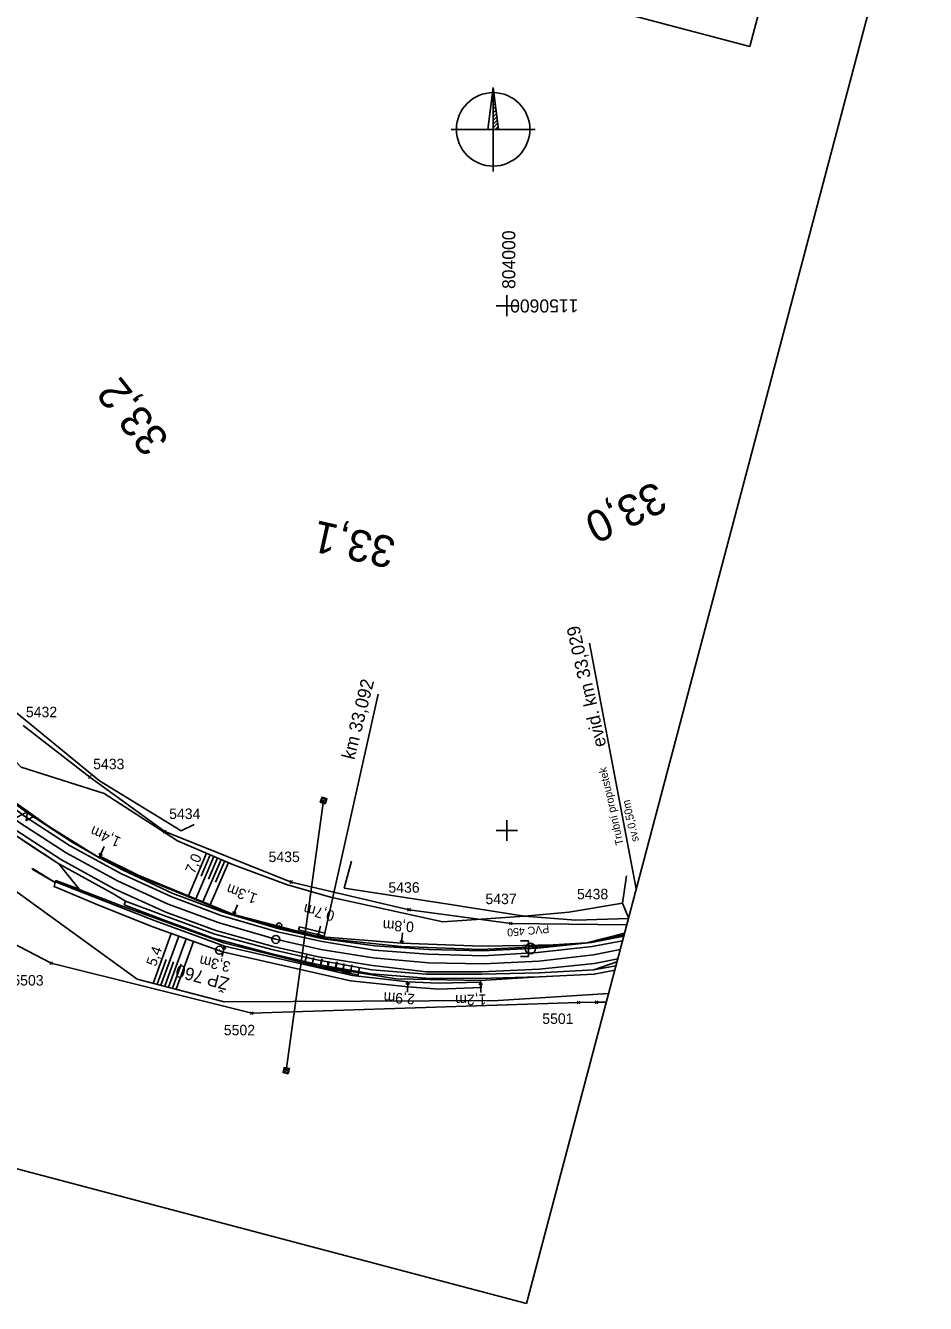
# Model space of a CAD drawing. Extents: x -805011 to -803920, y -1150790 to -1150234.
# Drawn here: x -804091.7 to -803920.3, y -1150790.1 to -1150546.6 of the extents above; entities that cross this region are included whole.
import ezdxf

# ---------------------------------------------------------------- set-up
doc = ezdxf.new("R2010")
doc.units = 0
for name, color, linetype in [('0381KM032-037P - Vrstva 1', 7, 'Continuous'), ('0381KM032-037P - Vrstva 11', 7, 'Continuous'), ('0381KM032-037P - Vrstva 13', 7, 'Continuous'), ('0381KM032-037P - Vrstva 17', 7, 'Continuous'), ('0381KM032-037P - Vrstva 19', 7, 'Continuous'), ('0381KM032-037P - Vrstva 25', 7, 'Continuous'), ('0381KM032-037P - Vrstva 4', 7, 'Continuous'), ('0381KM032-037P - Vrstva 43', 7, 'Continuous'), ('0381KM032-037P - Vrstva 44', 7, 'Continuous'), ('0381KM032-037P - Vrstva 48', 7, 'Continuous'), ('0381KM032-037P - Vrstva 49', 7, 'Continuous'), ('0381KM032-037P - Vrstva 50', 7, 'Continuous'), ('0381KM032-037P - Vrstva 7', 7, 'Continuous'), ('0381KM032-037P - Vrstva 9', 7, 'Continuous'), ('Default', 7, 'Continuous'), ('formát', 7, 'Continuous'), ('krizky_1000 - souradnice', 7, 'Continuous'), ('krizky_1000 - Vrstva 1', 7, 'Continuous'), ('szdc - hran DP', 7, 'Continuous'), ('szdc - szdc_cislo', 7, 'Continuous'), ('szdc - szdc_krizek', 7, 'Continuous'), ('vyt_sit - stávající', 7, 'Continuous')]:
    doc.layers.add(name, color=color, linetype=linetype)

msp = doc.modelspace()

# ---------------------------------------------------------------- linework, layer by layer
at = {"layer": '0381KM032-037P - Vrstva 1'}
msp.add_lwpolyline([(-803978.41, -1150722.71), (-803983.51, -1150723.68), (-803993.92, -1150724.91), (-804004.46, -1150725.42), (-804014.95, -1150725.21), (-804025.47, -1150724.25), (-804035.41, -1150722.67), (-804044.08, -1150720.74), (-804054.77, -1150717.61), (-804064.47, -1150714.03), (-804074.16, -1150709.61), (-804083.95, -1150704.25), (-804092.73, -1150698.52), (-804098.22, -1150694.46), (-804106.33, -1150687.73), (-804113.82, -1150680.6), (-804121.06, -1150672.62)], dxfattribs=at)
at = {"layer": '0381KM032-037P - Vrstva 11'}
for p, q in [((-804034.26, -1150693.99), (-804035.54, -1150694.57)), ((-804034.75, -1150693.8), (-804035.36, -1150694.08)), ((-804034.44, -1150694.48), (-804035.04, -1150694.76)), ((-804041.41, -1150745.38), (-804042.6, -1150746.13)), ((-804041.93, -1150745.26), (-804042.49, -1150745.62)), ((-804041.53, -1150745.9), (-804042.08, -1150746.25))]:
    msp.add_line(p, q, dxfattribs=at)
for points in [[(-804034.6, -1150694.92), (-804035.54, -1150694.57), (-804035.19, -1150693.64), (-804034.25, -1150693.98)], [(-804041.63, -1150746.35), (-804042.61, -1150746.13), (-804042.39, -1150745.16), (-804041.41, -1150745.38)]]:
    msp.add_lwpolyline(points, close=True, dxfattribs=at)
at = {"layer": '0381KM032-037P - Vrstva 13'}
for p, q in [((-804076.66, -1150703.07), (-804077.51, -1150704.88)), ((-804090.31, -1150707.26), (-804090.39, -1150707.37)), ((-804086.01, -1150709.9), (-804090.31, -1150707.26)), ((-804090.39, -1150707.37), (-804086.01, -1150709.92)), ((-804086.01, -1150709.9), (-804085.89, -1150709.55)), ((-804085.98, -1150709.77), (-804085.89, -1150709.55)), ((-804086.01, -1150709.92), (-804086.01, -1150709.9)), ((-804051.27, -1150714.14), (-804052.03, -1150715.99)), ((-804035.82, -1150720.44), (-804051.93, -1150716.22)), ((-804035.5, -1150718.26), (-804035.97, -1150720.21)), ((-804019.87, -1150719.5), (-804020.03, -1150721.49)), ((-804054.2, -1150724.02), (-804053.75, -1150722.07)), ((-804018.95, -1150730.84), (-804018.83, -1150728.85)), ((-804004.99, -1150728.9), (-804004.87, -1150729.93)), ((-804004.95, -1150730.9), (-804004.99, -1150728.9))]:
    msp.add_line(p, q, dxfattribs=at)
for points in [[(-804052.03, -1150715.99), (-804070.24, -1150708.52), (-804077.53, -1150704.87), (-804077.68, -1150705.14), (-804070.39, -1150708.64), (-804052.3, -1150716.03), (-804051.93, -1150716.22)], [(-804077.57, -1150704.3), (-804077.51, -1150704.88), (-804077.03, -1150704.55)], [(-804085.89, -1150709.55), (-804073.05, -1150714.48), (-804053.9, -1150721.4), (-804036.64, -1150725.7), (-804021.1, -1150728.28), (-804004.99, -1150728.61), (-804004.87, -1150729.93)], [(-804085.98, -1150709.77), (-804086.01, -1150709.92), (-804086.24, -1150710.7)], [(-804004.87, -1150729.93), (-804012.98, -1150730.26), (-804018.76, -1150729.81), (-804029.79, -1150728.64), (-804054.15, -1150723.15), (-804067.44, -1150718.36), (-804077.42, -1150714.36), (-804086.24, -1150710.7)], [(-804004.99, -1150728.9), (-804013.04, -1150729.07), (-804018.83, -1150728.85), (-804029.4, -1150727.62), (-804053.75, -1150722.07), (-804066.98, -1150717.23), (-804077.05, -1150713.27), (-804085.98, -1150709.77)], [(-804072.89, -1150714.19), (-804072.63, -1150713.44), (-804065.3, -1150716.18), (-804055.61, -1150719.76), (-804044.75, -1150722.66), (-804036.16, -1150724.67), (-804025.7, -1150726.54), (-804015.38, -1150727.38), (-804004.78, -1150727.4), (-803993.85, -1150727.11), (-803983.42, -1150726.57), (-803979.23, -1150725.8)], [(-803979.45, -1150726.65), (-803983.37, -1150727.37), (-803993.84, -1150727.91), (-804005.29, -1150728.22), (-804015.43, -1150728.15), (-804025.86, -1150727.31), (-804036.32, -1150725.46), (-804045.02, -1150723.43), (-804055.91, -1150720.49), (-804065.55, -1150716.94), (-804072.89, -1150714.19)], [(-804052.11, -1150715.42), (-804052.03, -1150715.99), (-804051.56, -1150715.64)], [(-803991.2, -1150721.8), (-803996.89, -1150721.92), (-804004.84, -1150722.06), (-804020.03, -1150721.49), (-804035.97, -1150720.21), (-804052.03, -1150715.99)], [(-804036.15, -1150719.65), (-804035.97, -1150720.21), (-804035.56, -1150719.79)], [(-803991.2, -1150721.8), (-803997.06, -1150722.33), (-804004.97, -1150722.65), (-804020.12, -1150722.09), (-804035.82, -1150720.44)], [(-804020.29, -1150720.97), (-804020.03, -1150721.49), (-804019.69, -1150721.02)], [(-804053.57, -1150722.62), (-804053.75, -1150722.07), (-804054.16, -1150722.49)], [(-804018.56, -1150729.36), (-804018.83, -1150728.85), (-804019.16, -1150729.33)], [(-804004.68, -1150729.4), (-804004.99, -1150728.9), (-804005.28, -1150729.41)], [(-804004.99, -1150728.9), (-804004.99, -1150728.9), (-804004.99, -1150728.9), (-804004.99, -1150728.61)]]:
    msp.add_lwpolyline(points, dxfattribs=at)
at = {"layer": '0381KM032-037P - Vrstva 17'}
for points in [[(-804059.54, -1150698.86), (-804062.04, -1150700.07), (-804077.59, -1150690.55), (-804099.12, -1150672.95)], [(-803996.63, -1150716.3), (-804006.34, -1150714.83), (-804011.55, -1150713.97), (-804030.97, -1150711.02), (-804029.61, -1150705.83)], [(-803977.22, -1150708.65), (-803977.99, -1150713.83)], [(-803977.99, -1150713.83), (-803976.8, -1150716.64)], [(-803976.84, -1150716.79), (-803986.83, -1150717.08), (-803996.63, -1150716.3)]]:
    msp.add_lwpolyline(points, dxfattribs=at)
at = {"layer": '0381KM032-037P - Vrstva 19'}
msp.add_line((-803975.34, -1150711.1), (-803984.23, -1150664.27), dxfattribs=at)
at = {"layer": '0381KM032-037P - Vrstva 25'}
msp.add_line((-804034.9, -1150694.28), (-804042.01, -1150745.75), dxfattribs=at)
at = {"layer": '0381KM032-037P - Vrstva 4'}
for points in [[(-804073.38, -1150708.29), (-804083.27, -1150702.88), (-804091.89, -1150697.28), (-804097.27, -1150693.2), (-804105.34, -1150686.53), (-804112.64, -1150679.57), (-804120.03, -1150671.79), (-804126.35, -1150663.48), (-804132.06, -1150655.06)], [(-804073.1, -1150707.59), (-804077.68, -1150705.14), (-804082.78, -1150702.25), (-804091.44, -1150696.56), (-804096.83, -1150692.65), (-804104.73, -1150685.98), (-804112.1, -1150679.17), (-804119.6, -1150671.34), (-804125.86, -1150663.1), (-804131.6, -1150654.76)], [(-804075.18, -1150711.95), (-804085.34, -1150706.36), (-804094.07, -1150700.58), (-804099.68, -1150696.17), (-804107.82, -1150689.29), (-804115.4, -1150682.25), (-804122.72, -1150674.01), (-804129.15, -1150665.64), (-804135, -1150656.89)], [(-804074.79, -1150711.15), (-804084.84, -1150705.62), (-804093.69, -1150699.81), (-804099.23, -1150695.65), (-804107.33, -1150688.8), (-804114.94, -1150681.73), (-804122.23, -1150673.64), (-804128.61, -1150665.3), (-804134.56, -1150656.61)], [(-803977.96, -1150721), (-803983.73, -1150722.13), (-803994.13, -1150723.26), (-804004.52, -1150723.87), (-804015.05, -1150723.54), (-804025.27, -1150722.78), (-804035.17, -1150721.13), (-804043.67, -1150719.32), (-804054.39, -1150716.19), (-804063.83, -1150712.64), (-804073.38, -1150708.29)], [(-803977.73, -1150720.15), (-803983.88, -1150721.36), (-803994.18, -1150722.4), (-804004.64, -1150722.95), (-804014.86, -1150722.69), (-804025.14, -1150721.99), (-804034.98, -1150720.62), (-804043.41, -1150718.77), (-804051.93, -1150716.22), (-804054.24, -1150715.48), (-804063.6, -1150711.99), (-804073.1, -1150707.59)], [(-803979.03, -1150725.06), (-803983.42, -1150726.57), (-803993.85, -1150727.11), (-804004.78, -1150727.4), (-804015.38, -1150727.38), (-804025.7, -1150726.54), (-804036.16, -1150724.67), (-804044.75, -1150722.66), (-804055.61, -1150719.76), (-804065.3, -1150716.18), (-804072.63, -1150713.44), (-804075.18, -1150711.95)], [(-803978.88, -1150724.49), (-803983.32, -1150725.37), (-803993.82, -1150726.43), (-804004.8, -1150726.96), (-804015.29, -1150726.92), (-804025.6, -1150725.76), (-804035.88, -1150724.11), (-804044.5, -1150722.13), (-804055.4, -1150719.07), (-804064.95, -1150715.56), (-804074.79, -1150711.15)]]:
    msp.add_lwpolyline(points, dxfattribs=at)
at = {"layer": '0381KM032-037P - Vrstva 43'}
for points in [[(-803997.39, -1150721.01), (-803995.89, -1150721.01), (-803995.89, -1150724.01), (-803997.39, -1150724.01)], [(-804035.17, -1150724.55), (-804035.58, -1150726), (-804038.46, -1150725.19), (-804038.06, -1150723.74)], [(-804033.84, -1150725), (-804034.23, -1150726.45), (-804037.12, -1150725.67), (-804036.73, -1150724.22)], [(-804032.32, -1150725.04), (-804032.63, -1150726.51), (-804035.56, -1150725.9), (-804035.26, -1150724.43)], [(-804031.05, -1150725.35), (-804031.24, -1150726.84), (-804034.22, -1150726.45), (-804034.02, -1150724.96)], [(-804029.49, -1150725.62), (-804029.77, -1150727.09), (-804032.72, -1150726.52), (-804032.43, -1150725.05)], [(-804028.05, -1150726.05), (-804028.31, -1150727.53), (-804031.27, -1150727.01), (-804031.01, -1150725.53)]]:
    msp.add_lwpolyline(points, dxfattribs=at)
msp.add_circle((-803995.51, -1150722.5), 1, dxfattribs=at)
at = {"layer": '0381KM032-037P - Vrstva 44'}
msp.add_lwpolyline([(-803995.89, -1150722.51), (-803984.82, -1150721.44), (-803977.57, -1150719.55)], dxfattribs=at)
at = {"layer": '0381KM032-037P - Vrstva 48'}
for p, q in [((-804057.18, -1150704.34), (-804060.65, -1150712.45)), ((-804056.49, -1150704.63), (-804058.22, -1150708.69)), ((-804055.8, -1150704.93), (-804059.26, -1150713.02)), ((-804054.42, -1150705.52), (-804057.88, -1150713.59)), ((-804055.11, -1150705.22), (-804056.84, -1150709.27)), ((-804053.04, -1150706.11), (-804056.49, -1150714.16)), ((-804053.73, -1150705.81), (-804055.46, -1150709.84)), ((-804067.33, -1150729.13), (-804063.91, -1150719.64)), ((-804065.87, -1150729.51), (-804062.5, -1150720.14)), ((-804064.41, -1150729.89), (-804061.08, -1150720.65)), ((-804062.95, -1150730.26), (-804059.67, -1150721.16)), ((-804066.6, -1150729.32), (-804064.9, -1150724.6)), ((-804065.14, -1150729.7), (-804063.46, -1150725.05)), ((-804063.68, -1150730.07), (-804062.03, -1150725.49))]:
    msp.add_line(p, q, dxfattribs=at)
at = {"layer": '0381KM032-037P - Vrstva 49'}
msp.add_line((-804001.62, -1150732.39), (-803980.62, -1150731.04), dxfattribs=at)
for points in [[(-804216.26, -1150515.03), (-804196.49, -1150533.54), (-804188.66, -1150542.31), (-804183.72, -1150548.22), (-804177, -1150556.4), (-804165.66, -1150573.06), (-804155.49, -1150590.5), (-804146.45, -1150604.86), (-804136.37, -1150622.31), (-804131.91, -1150629.82), (-804122.71, -1150645.64), (-804115.71, -1150666.79), (-804102.89, -1150677.06), (-804092.51, -1150687.92), (-804076.71, -1150692.97), (-804062.72, -1150701.97), (-804052.08, -1150706.52)], [(-804191.88, -1150555.68), (-804187.09, -1150562.15), (-804183.47, -1150572.06), (-804177.47, -1150586.83), (-804171.32, -1150602.68), (-804162.19, -1150629.63), (-804127.41, -1150694.05), (-804117.85, -1150694.76), (-804107.49, -1150702.04), (-804103.03, -1150704.73), (-804070.42, -1150728.33), (-804053.81, -1150732.63), (-804001.62, -1150732.39)], [(-804171.89, -1150581.01), (-804161.29, -1150603.14), (-804153.71, -1150619.99), (-804149.71, -1150629.27), (-804147.81, -1150633.31), (-804145.48, -1150638.07), (-804140.73, -1150647.62), (-804139.02, -1150650.67), (-804131.55, -1150663.46), (-804125.32, -1150670.91), (-804120.07, -1150678.75), (-804110.3, -1150687.62), (-804101.36, -1150694.88), (-804099.68, -1150696.17), (-804094.07, -1150700.58), (-804090.5, -1150703.01), (-804085.34, -1150706.36), (-804081.43, -1150711.18)], [(-804115.86, -1150674.86), (-804107.6, -1150683.08), (-804103.3, -1150684.96), (-804098.16, -1150691.46), (-804087.29, -1150699.16)], [(-804087.29, -1150699.16), (-804077.68, -1150705.14), (-804077.53, -1150704.87), (-804070.24, -1150708.52), (-804052.03, -1150715.99)], [(-803977.22, -1150708.65), (-803977.99, -1150713.83), (-803988.17, -1150715.55), (-803996.63, -1150716.3), (-804012.18, -1150717.41), (-804033.61, -1150712.69), (-804041.95, -1150710.32), (-804052.08, -1150706.52)], [(-804086.01, -1150709.92), (-804086.01, -1150709.9), (-804085.89, -1150709.55), (-804081.43, -1150711.18)], [(-803979.45, -1150726.65), (-803983.37, -1150727.37), (-803993.84, -1150727.91), (-804004.99, -1150728.61), (-804004.87, -1150729.93), (-804012.98, -1150730.26), (-804018.76, -1150729.81), (-804029.79, -1150728.64), (-804054.15, -1150723.15), (-804067.44, -1150718.36), (-804077.42, -1150714.36), (-804086.24, -1150710.7), (-804086.01, -1150709.92)], [(-803984.82, -1150721.44), (-803991.2, -1150721.8), (-803996.89, -1150721.92), (-804004.84, -1150722.06), (-804020.03, -1150721.49), (-804035.97, -1150720.21), (-804052.03, -1150715.99)], [(-803984.82, -1150721.44), (-803977.66, -1150719.89)]]:
    msp.add_lwpolyline(points, dxfattribs=at)
at = {"layer": '0381KM032-037P - Vrstva 50'}
msp.add_lwpolyline([(-804090.07, -1150697.33), (-804091.56, -1150698.09), (-804091.28, -1150696.44), (-804094.26, -1150697.96), (-804093.69, -1150694.66)], dxfattribs=at)
at = {"layer": '0381KM032-037P - Vrstva 7'}
msp.add_line((-804043.32, -1150718.13), (-804043.42, -1150718.1), dxfattribs=at)
for centre, radius in [((-804043.37, -1150718.12), 0.5), ((-804043.99, -1150720.76), 0.75)]:
    msp.add_circle(centre, radius, dxfattribs=at)
at = {"layer": '0381KM032-037P - Vrstva 9'}
for p, q in [((-804034.8, -1150720.15), (-804024.5, -1150674.02)), ((-804039.51, -1150718.34), (-804039.66, -1150718.92)), ((-804039.66, -1150718.92), (-804034.81, -1150720.14)), ((-804034.66, -1150719.56), (-804039.51, -1150718.34)), ((-804034.66, -1150719.56), (-804034.52, -1150718.98)), ((-804034.81, -1150720.14), (-804034.66, -1150719.56))]:
    msp.add_line(p, q, dxfattribs=at)
at = {"layer": 'Default'}
msp.add_lwpolyline([(-803953.74, -1150550.58), (-804040.97, -1150527.49), (-804028.88, -1150481.79), (-803941.64, -1150504.87)], close=True, dxfattribs=at)
at = {"layer": 'formát'}
for p, q in [((-803920.28, -1150503.02), (-803996.25, -1150790.14)), ((-804002.61, -1150558.37), (-804002.61, -1150574.37)), ((-804002.61, -1150559.01), (-804002.54, -1150558.94)), ((-804002.61, -1150559.72), (-804002.47, -1150559.57)), ((-804002.61, -1150560.42), (-804002.39, -1150560.19)), ((-804002.61, -1150561.13), (-804002.31, -1150560.82)), ((-804002.61, -1150561.84), (-804002.23, -1150561.45)), ((-804002.61, -1150562.54), (-804002.15, -1150562.08)), ((-804002.61, -1150563.25), (-804002.07, -1150562.71)), ((-804002.61, -1150563.96), (-804001.99, -1150563.34)), ((-804002.61, -1150564.67), (-804001.92, -1150563.97)), ((-804002.61, -1150565.37), (-804001.84, -1150564.59)), ((-804002.61, -1150566.08), (-804001.76, -1150565.22)), ((-804002.2, -1150566.37), (-804001.68, -1150565.85)), ((-804010.61, -1150566.37), (-803994.61, -1150566.37)), ((-803996.25, -1150790.14), (-804199.27, -1150736.42))]:
    msp.add_line(p, q, dxfattribs=at)
for points in [[(-804002.61, -1150558.37), (-804003.61, -1150566.37)], [(-804002.61, -1150558.37), (-804001.61, -1150566.37)], [(-804002.61, -1150558.37), (-804002.61, -1150566.37), (-804001.61, -1150566.37), (-804002.61, -1150558.37)]]:
    msp.add_lwpolyline(points, dxfattribs=at)
msp.add_circle((-804002.61, -1150566.37), 7, dxfattribs=at)
at = {"layer": 'krizky_1000 - Vrstva 1'}
for points in [[(-804002, -1150600), (-803998, -1150600)], [(-804000, -1150598), (-804000, -1150602)], [(-804002, -1150700), (-803998, -1150700)], [(-804000, -1150698), (-804000, -1150702)]]:
    msp.add_lwpolyline(points, dxfattribs=at)
at = {"layer": 'szdc - hran DP'}
for p, q in [((-804092.1, -1150680), (-804079.43, -1150689.81)), ((-804079.43, -1150689.81), (-804065.16, -1150700.21)), ((-804065.16, -1150700.21), (-804041.05, -1150709.83)), ((-804041.05, -1150709.83), (-804018.63, -1150715.09)), ((-804018.63, -1150715.09), (-803999.22, -1150717.72)), ((-804086.77, -1150725.31), (-804098.25, -1150719.35)), ((-803999.22, -1150717.72), (-803977.16, -1150717.98)), ((-804048.58, -1150734.81), (-804086.77, -1150725.31)), ((-803986.36, -1150732.8), (-804048.58, -1150734.81)), ((-803982.91, -1150732.74), (-803986.36, -1150732.8)), ((-803981.05, -1150732.7), (-803982.91, -1150732.74))]:
    msp.add_line(p, q, dxfattribs=at)
at = {"layer": 'szdc - szdc_krizek'}
for p, q in [((-804079.17, -1150690.07), (-804079.7, -1150689.54)), ((-804079.7, -1150690.07), (-804079.17, -1150689.54)), ((-804064.9, -1150700.48), (-804065.43, -1150699.95)), ((-804065.43, -1150700.48), (-804064.9, -1150699.95)), ((-804040.79, -1150710.09), (-804041.32, -1150709.56)), ((-804041.32, -1150710.09), (-804040.79, -1150709.56)), ((-804018.36, -1150715.35), (-804018.9, -1150714.82)), ((-804018.9, -1150715.35), (-804018.36, -1150714.82)), ((-803998.96, -1150717.99), (-803999.49, -1150717.46)), ((-803999.49, -1150717.99), (-803998.96, -1150717.46)), ((-803977.1, -1150717.78), (-803977.17, -1150717.72)), ((-804086.51, -1150725.57), (-804087.04, -1150725.04)), ((-804087.04, -1150725.57), (-804086.51, -1150725.04)), ((-803986.09, -1150733.06), (-803986.63, -1150732.53)), ((-803986.63, -1150733.06), (-803986.09, -1150732.53)), ((-803982.65, -1150733.01), (-803983.18, -1150732.48)), ((-803983.18, -1150733.01), (-803982.65, -1150732.48)), ((-804048.32, -1150735.07), (-804048.85, -1150734.54)), ((-804048.85, -1150735.07), (-804048.32, -1150734.54))]:
    msp.add_line(p, q, dxfattribs=at)
at = {"layer": 'vyt_sit - stávající'}
msp.add_line((-804054.77, -1150722.82), (-804054.67, -1150722.82), dxfattribs=at)
msp.add_circle((-804054.72, -1150722.82), 0.756, dxfattribs=at)

# ---------------------------------------------------------------- texts
at = {"layer": '0381KM032-037P - Vrstva 13'}
for s, rotation, p in [('1,4m', 156.1294, (-804073.33, -1150701.45)), ('1,3m', 159.4135, (-804047.36, -1150712.19)), ('0,7m', 165.6438, (-804032.66, -1150715.41)), ('0,8m', 176.7126, (-804017.65, -1150717.4)), ('3,3m', 167.1636, (-804052.49, -1150725.09)), ('2,9m', 176.4791, (-804017.48, -1150731.17)), ('1,2m', 181.2027, (-804003.91, -1150731.23))]:
    msp.add_text(s, height=2, rotation=rotation, dxfattribs=at).set_placement(p)
at = {"layer": '0381KM032-037P - Vrstva 19'}
for s, height, p in [('evid. km 33,029', 2.5, (-803981.04, -1150683.82)), ('Trubní propustek', 1.5, (-803977.75, -1150702.64)), ('sv.0,50m', 1.5, (-803974.83, -1150701.98))]:
    msp.add_text(s, height=height, rotation=102.69, dxfattribs=at).set_placement(p)
at = {"layer": '0381KM032-037P - Vrstva 43'}
msp.add_text('PVC 450', height=1.5, rotation=185, dxfattribs=at).set_placement((-803991.99, -1150718.03))
at = {"layer": '0381KM032-037P - Vrstva 48'}
for s, rotation, p in [('7,0', 66.8248, (-804059.51, -1150708.39)), ('5,4', 70.2002, (-804066.86, -1150726.04))]:
    msp.add_text(s, height=2, rotation=rotation, dxfattribs=at).set_placement(p)
at = {"layer": '0381KM032-037P - Vrstva 7'}
for s, rotation, p in [('33,2', 128.139, (-804064.09, -1150625.46)), ('33,0', 205.6225, (-803971.56, -1150633.32)), ('33,1', 167.4012, (-804020.85, -1150644.28))]:
    msp.add_text(s, height=6, rotation=rotation, dxfattribs=at).set_placement(p)
at = {"layer": '0381KM032-037P - Vrstva 9'}
msp.add_text('km 33,092', height=2.5, rotation=75.8763, dxfattribs=at).set_placement((-804029.06, -1150686.64))
at = {"layer": 'krizky_1000 - souradnice'}
for s, rotation, p in [('804000', 90, (-803998.38, -1150596.79)), ('1150600', 180, (-803986.36, -1150598.77))]:
    msp.add_text(s, height=2.5, rotation=rotation, dxfattribs=at).set_placement(p)
at = {"layer": 'szdc - szdc_cislo'}
for s, p in [('5432', (-804091.59, -1150678.41)), ('5433', (-804078.79, -1150688.33)), ('5434', (-804064.31, -1150697.81)), ('5435', (-804045.38, -1150706.02)), ('5436', (-804022.56, -1150711.86)), ('5437', (-804004.08, -1150714.04)), ('5438', (-803986.64, -1150713.12)), ('5503', (-804094.18, -1150729.55)), ('5501', (-803993.25, -1150736.86)), ('5502', (-804053.9, -1150739.04))]:
    msp.add_text(s, height=2, dxfattribs=at).set_placement(p)
at = {"layer": 'vyt_sit - stávající'}
msp.add_text('ŽP 760', height=2.4, rotation=165, dxfattribs=at).set_placement((-804052.69, -1150728.18))

doc.saveas('drawing.dxf')
